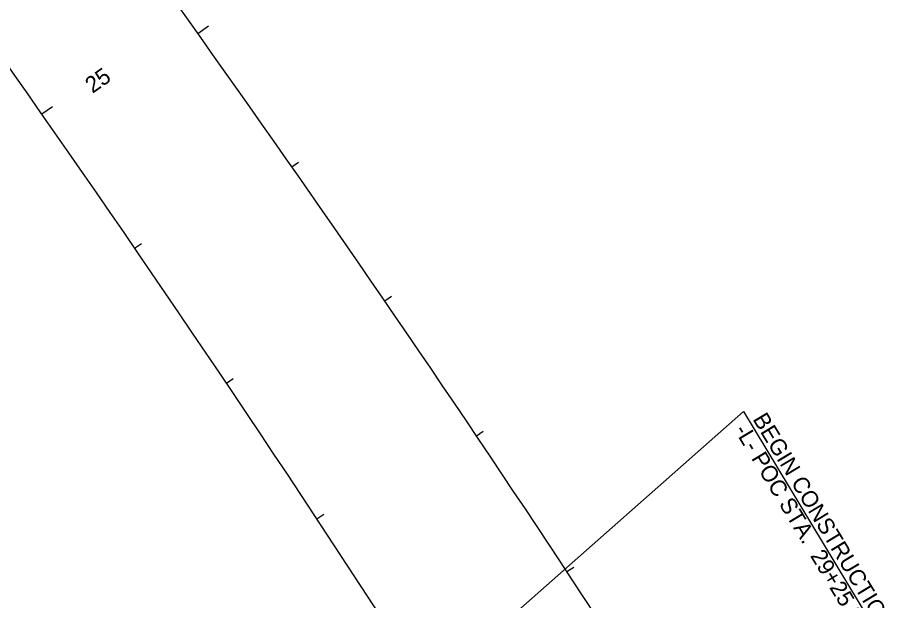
# Model space of a CAD drawing. Extents: x 1778969 to 1790720, y 807089 to 817794.
# Drawn here: x 1779937 to 1780475, y 816090 to 816447 of the extents above; entities that cross this region are included whole.
import ezdxf

# ---------------------------------------------------------------- set-up
doc = ezdxf.new("R2010")
doc.units = 0
for name, color, linetype in [('Prop Horizontal Alignment', 7, 'Continuous'), ('Prop Horizontal Alignment Station Label', 7, 'Continuous'), ('Prop Horizontal Alignment Tick Label', 7, 'Continuous'), ('Prop Horizontal Alignment Tick Large', 7, 'Continuous'), ('Prop Horizontal Alignment Tick Small', 7, 'Continuous')]:
    doc.layers.add(name, color=color, linetype=linetype)

msp = doc.modelspace()

# ---------------------------------------------------------------- linework, layer by layer
at = {"layer": 'Prop Horizontal Alignment'}
for centre, start in [((1770559.26, 809824.09), 31.75), ((1770559.26, 809824.09), 31.75), ((1770712.82, 809791.32), 32.966667)]:
    msp.add_arc(centre, 11459.16, start, 41.283333, dxfattribs=at)
at = {"layer": 'Prop Horizontal Alignment Station Label'}
for p, q in [((1780188.87, 816035.61), (1780381.93, 816206.15)), ((1780381.93, 816206.15), (1780469.18, 816061.61))]:
    msp.add_line(p, q, dxfattribs=at)
at = {"layer": 'Prop Horizontal Alignment Tick Large'}
for p, q in [((1780047.55, 816437.76), (1780054.06, 816442.4)), ((1779951.92, 816388.4), (1779958.48, 816392.99))]:
    msp.add_line(p, q, dxfattribs=at)
at = {"layer": 'Prop Horizontal Alignment Tick Small'}
for p, q in [((1780105.19, 816356.05), (1780109.29, 816358.91)), ((1780008.85, 816306.19), (1780012.97, 816309.02)), ((1780162.12, 816273.84), (1780166.24, 816276.66)), ((1780065.05, 816223.48), (1780069.2, 816226.27)), ((1780218.33, 816191.13), (1780222.48, 816193.92)), ((1780120.54, 816140.28), (1780124.71, 816143.04)), ((1780273.82, 816107.94), (1780277.99, 816110.69))]:
    msp.add_line(p, q, dxfattribs=at)

# ---------------------------------------------------------------- texts
at = {"layer": 'Prop Horizontal Alignment Station Label'}
for s, p in [('BEGIN CONSTRUCTION', (1780387.35, 816201.38)), ('-L- POC STA.  29+25.00', (1780376.13, 816194.6))]:
    msp.add_text(s, height=10, rotation=301.1652, dxfattribs=at).set_placement(p)
at = {"layer": 'Prop Horizontal Alignment Tick Label'}
msp.add_text('25', height=10, rotation=34.9488, dxfattribs=at).set_placement((1779983.01, 816400.7))

doc.saveas('drawing.dxf')
